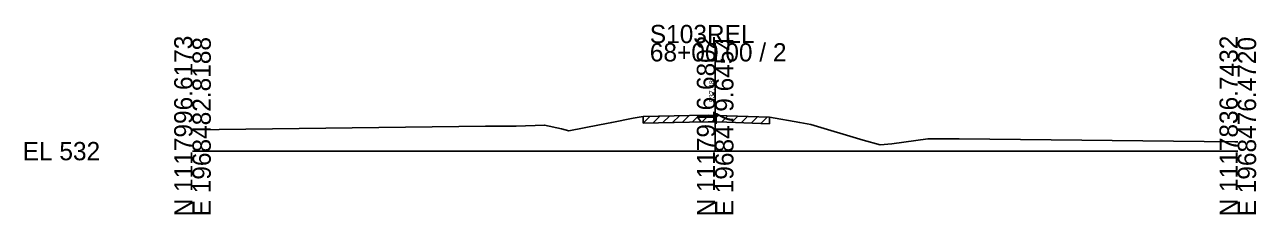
# Model space of a CAD drawing. Extents: x -26 to 163, y -10 to 24518.
# Drawn here: x -25.7 to 162.8, y 16490.3 to 16519.4 of the extents above; entities that cross this region are included whole.
import ezdxf

# ---------------------------------------------------------------- set-up
doc = ezdxf.new("R2010")
doc.units = 0
for name, color, linetype in [('RD_GPK_XS_Cell', 7, 'Continuous'), ('RD_XS_ExGround', 7, 'Continuous'), ('RD_XS_ExPaveRet', 7, 'Continuous'), ('RD_XS_TX_Elev_EX', 7, 'Continuous')]:
    doc.layers.add(name, color=color, linetype=linetype)

msp = doc.modelspace()

# ---------------------------------------------------------------- linework, layer by layer
at = {"layer": 'RD_GPK_XS_Cell'}
for p, q in [((80, 16500), (80, 16516.54)), ((0, 16500), (80, 16500)), ((80, 16500), (160, 16500))]:
    msp.add_line(p, q, dxfattribs=at)
at = {"layer": 'RD_XS_ExGround'}
msp.add_lwpolyline([(0, 16503.27), (44.87, 16503.84), (49.53, 16503.83), (53.88, 16503.99), (56.48, 16503.42), (57.59, 16503.13), (62.3, 16504.03), (64.18, 16504.41), (67.47, 16505.03), (68.99, 16505.29), (76.08, 16505.45), (78.94, 16505.51), (80, 16505.48), (81.79, 16505.42), (88.3, 16505.2), (92.96, 16504.38), (94.63, 16504.09), (102.66, 16501.66), (105.25, 16500.96), (107.06, 16501.11), (112.53, 16501.9), (117.34, 16501.89), (159.52, 16501.41), (160, 16501.41)], dxfattribs=at)
at = {"layer": 'RD_XS_ExPaveRet'}
for p, q in [((68.99, 16504.29), (70.02, 16505.31)), ((68.99, 16504.29), (68.99, 16505.29)), ((68.99, 16504.29), (76.08, 16504.45)), ((70.49, 16504.32), (71.52, 16505.35)), ((71.99, 16504.36), (73.02, 16505.38)), ((73.49, 16504.39), (74.52, 16505.42)), ((74.99, 16504.43), (76.02, 16505.45)), ((76.08, 16504.45), (78.94, 16504.51)), ((76.49, 16504.46), (77.51, 16505.48)), ((77.99, 16504.49), (79.01, 16505.51)), ((78.94, 16504.51), (80, 16504.48)), ((79.49, 16504.5), (80.46, 16505.46)), ((80, 16504.48), (81.79, 16504.42)), ((80.99, 16504.45), (81.96, 16505.41)), ((81.79, 16504.42), (88.3, 16504.2)), ((82.49, 16504.4), (83.46, 16505.36)), ((83.99, 16504.35), (84.96, 16505.31)), ((85.49, 16504.3), (86.46, 16505.26)), ((86.99, 16504.25), (87.96, 16505.22)), ((88.3, 16505.2), (88.3, 16504.2))]:
    msp.add_line(p, q, dxfattribs=at)

# ---------------------------------------------------------------- texts
at = {"layer": 'RD_GPK_XS_Cell'}
for s, p in [('S103REL', (70, 16516.54)), ('68+00.00 / 2', (70, 16513.74)), ('EL 532', (-26, 16498.6))]:
    msp.add_text(s, height=2.8, dxfattribs=at).set_placement(p)
for s, p in [('N 1117996.6173', (0, 16490)), ('N 1117916.6802', (80, 16490)), ('E 1968479.6454', (82.8, 16490)), ('N 1117836.7432', (160, 16490)), ('E 1968482.8188', (2.8, 16490)), ('E 1968476.4720', (162.8, 16490))]:
    msp.add_text(s, height=2.8, rotation=90, dxfattribs=at).set_placement(p)
at = {"layer": 'RD_XS_TX_Elev_EX'}
msp.add_text('537.48', height=0.8, rotation=90, dxfattribs=at).set_placement((79.9, 16507.48))

doc.saveas('drawing.dxf')
